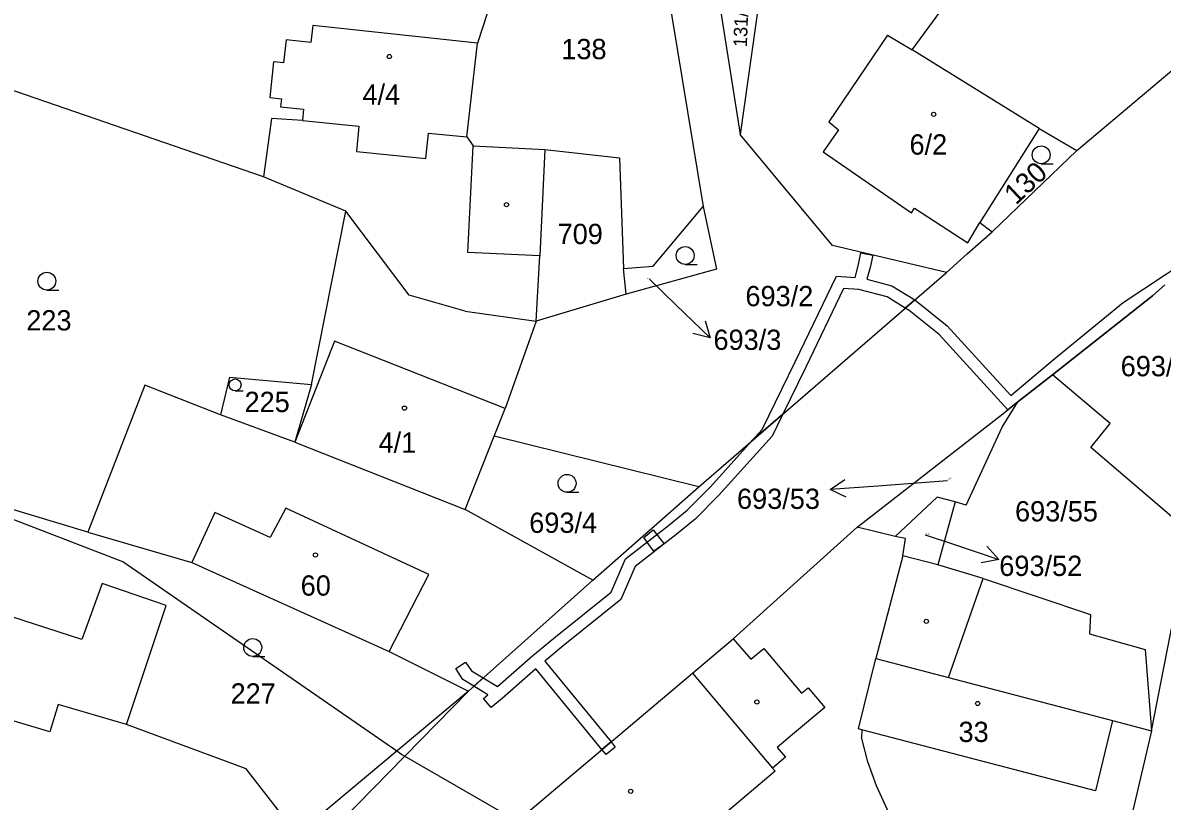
# Model space of a CAD drawing. Extents: x -747333 to -745433, y -1133152 to -1130600.
# Drawn here: x -746537.7 to -746442.1, y -1132077.2 to -1132011.9 of the extents above; entities that cross this region are included whole.
import ezdxf

# ---------------------------------------------------------------- set-up
doc = ezdxf.new("R2010")
doc.units = 0
for name, color, linetype in [('Vrstva 1', 7, 'Continuous'), ('Vrstva 16', 7, 'Continuous'), ('Vrstva 18', 7, 'Continuous'), ('Vrstva 19', 7, 'Continuous'), ('Vrstva 25', 7, 'Continuous'), ('Vrstva 3', 7, 'Continuous'), ('Vrstva 30', 7, 'Continuous'), ('Vrstva 37', 7, 'Continuous'), ('Vrstva 4', 7, 'Continuous'), ('Vrstva 52', 7, 'Continuous'), ('Vrstva 6', 7, 'Continuous')]:
    doc.layers.add(name, color=color, linetype=linetype)

msp = doc.modelspace()

# ---------------------------------------------------------------- linework, layer by layer
at = {"layer": 'Vrstva 1'}
msp.add_line((-746464.74, -1132078.87), (-746466.1, -1132075.88), dxfattribs=at)
for points in [[(-746485.89, -1131995.45), (-746480.65, -1132027.32)], [(-746494.93, -1131999.39), (-746499.57, -1132013.64)], [(-746479.42, -1132009.41), (-746477.54, -1132021.27)], [(-746475.88, -1132009.57), (-746477.54, -1132021.27)], [(-746463.13, -1132014.2), (-746460.4, -1132010.51)], [(-746513.39, -1132012.14), (-746513.55, -1132013.58)], [(-746499.57, -1132013.64), (-746513.39, -1132012.14)], [(-746515.63, -1132013.35), (-746515.84, -1132015.29)], [(-746513.55, -1132013.58), (-746515.63, -1132013.35)], [(-746465.2, -1132012.95), (-746470.12, -1132020.21)], [(-746465.2, -1132012.95), (-746463.13, -1132014.2)], [(-746500.46, -1132021.48), (-746499.57, -1132013.64)], [(-746449.32, -1132022.63), (-746438.69, -1132013.68)], [(-746517.52, -1132024.84), (-746547.41, -1132014.55)], [(-746516.68, -1132015.19), (-746517, -1132018.17)], [(-746515.84, -1132015.29), (-746516.68, -1132015.19)], [(-746517, -1132018.17), (-746516.01, -1132018.28)], [(-746516.01, -1132018.28), (-746516.08, -1132018.96)], [(-746516.08, -1132018.96), (-746514.15, -1132019.17)], [(-746514.15, -1132019.17), (-746514.25, -1132020.11)], [(-746516.85, -1132019.93), (-746517.52, -1132024.84)], [(-746514.25, -1132020.11), (-746516.85, -1132019.93)], [(-746469.3, -1132020.9), (-746470.59, -1132022.75)], [(-746470.12, -1132020.21), (-746469.3, -1132020.9)], [(-746452.47, -1132020.78), (-746457.44, -1132028.67)], [(-746452.47, -1132020.78), (-746449.32, -1132022.63)], [(-746500.46, -1132021.48), (-746499.94, -1132022.24)], [(-746469.81, -1132030.6), (-746477.54, -1132021.27)], [(-746499.94, -1132022.24), (-746493.92, -1132022.53)], [(-746493.92, -1132022.53), (-746494.35, -1132031.46)], [(-746493.92, -1132022.53), (-746487.66, -1132023.23)], [(-746470.59, -1132022.75), (-746463.17, -1132027.85)], [(-746456.4, -1132029.43), (-746449.32, -1132022.63)], [(-746487.66, -1132023.23), (-746487.32, -1132032.51)], [(-746510.62, -1132027.7), (-746517.52, -1132024.84)], [(-746513.48, -1132042.23), (-746510.62, -1132027.7)], [(-746505.29, -1132034.76), (-746510.62, -1132027.7)], [(-746484.84, -1132032.33), (-746480.65, -1132027.32)], [(-746480.65, -1132027.32), (-746479.53, -1132032.56)], [(-746463.17, -1132027.85), (-746462.91, -1132027.46)], [(-746462.91, -1132027.46), (-746458.46, -1132030.36)], [(-746458.46, -1132030.36), (-746457.44, -1132028.67)], [(-746457.44, -1132028.67), (-746456.4, -1132029.43)], [(-746458.5, -1132031.29), (-746456.4, -1132029.43)], [(-746460.24, -1132032.84), (-746469.81, -1132030.6)], [(-746494.65, -1132036.93), (-746494.35, -1132031.46)], [(-746460.24, -1132032.84), (-746458.5, -1132031.29)], [(-746487.32, -1132032.51), (-746484.84, -1132032.33)], [(-746487.1, -1132034.68), (-746487.32, -1132032.51)], [(-746479.53, -1132032.56), (-746487.1, -1132034.68)], [(-746481.01, -1132050.82), (-746460.24, -1132032.84)], [(-746442.97, -1132034.81), (-746441.94, -1132033.89)], [(-746500.61, -1132036.09), (-746505.29, -1132034.76)], [(-746487.1, -1132034.68), (-746494.65, -1132036.93)], [(-746451.35, -1132041.44), (-746442.97, -1132034.81)], [(-746500.61, -1132036.09), (-746494.65, -1132036.93)], [(-746494.65, -1132036.93), (-746497.26, -1132044.25)], [(-746520.36, -1132041.62), (-746521.13, -1132044.79)], [(-746520.36, -1132041.62), (-746513.48, -1132042.23)], [(-746454.25, -1132043.7), (-746451.35, -1132041.44)], [(-746527.47, -1132042.31), (-746532.26, -1132054.61)], [(-746521.13, -1132044.79), (-746527.47, -1132042.31)], [(-746513.48, -1132042.23), (-746514.9, -1132047.08)], [(-746455.77, -1132044.89), (-746454.25, -1132043.7)], [(-746514.9, -1132047.08), (-746521.13, -1132044.79)], [(-746498.18, -1132046.57), (-746497.26, -1132044.25)], [(-746467.74, -1132054.2), (-746455.77, -1132044.89)], [(-746532.26, -1132054.61), (-746561.87, -1132045.71)], [(-746500.6, -1132052.72), (-746498.18, -1132046.57)], [(-746481.01, -1132050.82), (-746498.18, -1132046.57)], [(-746514.9, -1132047.08), (-746500.6, -1132052.72)], [(-746489.9, -1132058.63), (-746481.01, -1132050.82)], [(-746489.9, -1132058.63), (-746500.6, -1132052.72)], [(-746478.14, -1132063.56), (-746467.74, -1132054.2)], [(-746464.53, -1132054.98), (-746467.74, -1132054.2)], [(-746532.26, -1132054.61), (-746523.53, -1132057.16)], [(-746463.68, -1132055.15), (-746464.53, -1132054.98)], [(-746463.9, -1132056.59), (-746463.68, -1132055.15)], [(-746523.53, -1132057.16), (-746506.99, -1132064.63)], [(-746463.9, -1132056.59), (-746466.16, -1132065.2)], [(-746460.97, -1132057.37), (-746463.9, -1132056.59)], [(-746457.15, -1132058.5), (-746460.97, -1132057.37)], [(-746532.75, -1132063.63), (-746550.3, -1132057.95)], [(-746531.05, -1132058.91), (-746532.75, -1132063.63)], [(-746525.69, -1132060.77), (-746531.05, -1132058.91)], [(-746500.33, -1132067.94), (-746489.9, -1132058.63)], [(-746457.15, -1132058.5), (-746448.17, -1132061.53)], [(-746529.02, -1132070.74), (-746525.69, -1132060.77)], [(-746448.17, -1132061.53), (-746448.25, -1132063.14)], [(-746448.25, -1132063.14), (-746443.57, -1132064.45)], [(-746481.55, -1132066.44), (-746478.14, -1132063.56)], [(-746506.99, -1132064.63), (-746500.33, -1132067.94)], [(-746443.57, -1132064.45), (-746443.05, -1132071.26)], [(-746467.62, -1132071.1), (-746466.16, -1132065.2)], [(-746498.03, -1132080.35), (-746481.55, -1132066.44)], [(-746525.66, -1132093.79), (-746500.33, -1132067.94)], [(-746500.33, -1132067.94), (-746514.69, -1132079.97)], [(-746518.97, -1132074.45), (-746529.02, -1132070.74)], [(-746446.32, -1132070.4), (-746447.75, -1132076.29)], [(-746446.32, -1132070.4), (-746443.05, -1132071.26)], [(-746467.33, -1132071.18), (-746467.62, -1132071.1)], [(-746467.33, -1132071.18), (-746467.37, -1132071.81)], [(-746447.75, -1132076.29), (-746467.33, -1132071.18)], [(-746443.05, -1132071.26), (-746448.34, -1132093.81)], [(-746466.83, -1132073.88), (-746467.37, -1132071.81)], [(-746514.69, -1132079.97), (-746518.97, -1132074.45)], [(-746466.1, -1132075.88), (-746466.83, -1132073.88)]]:
    msp.add_lwpolyline(points, dxfattribs=at)
at = {"layer": 'Vrstva 16'}
for p, q in [((-746480.476833, -1132036.896154), (-746480.062733, -1132038.338729)), ((-746468.647811, -1132051.695755), (-746469.999255, -1132051.042992)), ((-746456.851891, -1132055.781943), (-746455.859647, -1132056.907977))]:
    msp.add_line(p, q, dxfattribs=at)
for points in [[(-746485.16, -1132033.41), (-746482.94, -1132035.56)], [(-746482.94, -1132035.56), (-746480.062733, -1132038.338729), (-746481.518856, -1132037.97513)], [(-746466.01, -1132050.75), (-746469.999255, -1132051.042992), (-746468.757683, -1132050.199785)], [(-746460.15, -1132050.32), (-746466.01, -1132050.75)], [(-746462.03, -1132054.83), (-746459.65, -1132055.63)], [(-746459.65, -1132055.63), (-746455.859647, -1132056.907977), (-746457.331132, -1132057.203326)]]:
    msp.add_lwpolyline(points, dxfattribs=at)
at = {"layer": 'Vrstva 25'}
for p, q in [((-746452.3, -1132023.74), (-746451.3, -1132023.74)), ((-746482.15, -1132032.18), (-746481.15, -1132032.18)), ((-746535.69, -1132034.33), (-746534.69, -1132034.33)), ((-746519.9, -1132042.78), (-746519.23, -1132042.78)), ((-746492.06, -1132051.28), (-746491.06, -1132051.28)), ((-746518.42, -1132065.04), (-746517.42, -1132065.04))]:
    msp.add_line(p, q, dxfattribs=at)
for centre, radius in [((-746506.97, -1132014.75), 0.174503), ((-746461.32, -1132019.59), 0.174503), ((-746452.3, -1132022.99), 0.75), ((-746497.14, -1132027.16), 0.174503), ((-746482.15, -1132031.43), 0.75), ((-746535.69, -1132033.58), 0.75), ((-746519.9, -1132042.2775), 0.5025), ((-746505.7, -1132044.22), 0.174503), ((-746492.06, -1132050.53), 0.75), ((-746513.16, -1132056.54), 0.174503), ((-746461.93, -1132062.09), 0.174503), ((-746518.42, -1132064.29), 0.75), ((-746476.14, -1132068.86), 0.174503), ((-746457.62, -1132068.98), 0.174503), ((-746486.72, -1132076.35), 0.174503)]:
    msp.add_circle(centre, radius, dxfattribs=at)
at = {"layer": 'Vrstva 3'}
for points in [[(-746513.39, -1132012.14), (-746513.55, -1132013.58)], [(-746499.57, -1132013.64), (-746513.39, -1132012.14)], [(-746515.63, -1132013.35), (-746515.84, -1132015.29)], [(-746513.55, -1132013.58), (-746515.63, -1132013.35)], [(-746465.2, -1132012.95), (-746470.12, -1132020.21)], [(-746465.2, -1132012.95), (-746463.13, -1132014.2)], [(-746500.46, -1132021.48), (-746499.57, -1132013.64)], [(-746452.47, -1132020.78), (-746463.13, -1132014.2)], [(-746516.68, -1132015.19), (-746517, -1132018.17)], [(-746515.84, -1132015.29), (-746516.68, -1132015.19)], [(-746517, -1132018.17), (-746516.01, -1132018.28)], [(-746516.01, -1132018.28), (-746516.08, -1132018.96)], [(-746516.08, -1132018.96), (-746514.15, -1132019.17)], [(-746514.15, -1132019.17), (-746514.25, -1132020.11)], [(-746514.25, -1132020.11), (-746509.52, -1132020.58)], [(-746509.52, -1132020.58), (-746509.73, -1132022.72)], [(-746469.3, -1132020.9), (-746470.59, -1132022.75)], [(-746470.12, -1132020.21), (-746469.3, -1132020.9)], [(-746452.47, -1132020.78), (-746457.44, -1132028.67)], [(-746503.91, -1132023.3), (-746503.69, -1132021.16)], [(-746503.69, -1132021.16), (-746500.46, -1132021.48)], [(-746509.73, -1132022.72), (-746503.91, -1132023.3)], [(-746470.59, -1132022.75), (-746463.17, -1132027.85)], [(-746463.17, -1132027.85), (-746462.91, -1132027.46)], [(-746462.91, -1132027.46), (-746458.46, -1132030.36)], [(-746458.46, -1132030.36), (-746457.44, -1132028.67)], [(-746511.56, -1132038.61), (-746514.9, -1132047.08)], [(-746497.26, -1132044.25), (-746511.56, -1132038.61)], [(-746498.18, -1132046.57), (-746497.26, -1132044.25)], [(-746500.6, -1132052.72), (-746498.18, -1132046.57)], [(-746514.9, -1132047.08), (-746500.6, -1132052.72)], [(-746515.64, -1132052.6), (-746516.95, -1132055.07)], [(-746503.66, -1132058.16), (-746515.64, -1132052.6)], [(-746521.59, -1132052.98), (-746523.53, -1132057.16)], [(-746516.95, -1132055.07), (-746521.59, -1132052.98)], [(-746523.53, -1132057.16), (-746506.99, -1132064.63)], [(-746506.99, -1132064.63), (-746503.66, -1132058.16)], [(-746467.62, -1132071.1), (-746466.16, -1132065.2)], [(-746466.16, -1132065.2), (-746460.07, -1132066.8)], [(-746498.03, -1132080.35), (-746481.55, -1132066.44)], [(-746481.55, -1132066.44), (-746474.84, -1132074.39)], [(-746460.07, -1132066.8), (-746446.32, -1132070.4)], [(-746446.32, -1132070.4), (-746447.75, -1132076.29)], [(-746467.33, -1132071.18), (-746467.62, -1132071.1)], [(-746447.75, -1132076.29), (-746467.33, -1132071.18)], [(-746474.84, -1132074.39), (-746474.61, -1132074.66)], [(-746475.14, -1132075.1), (-746479.87, -1132079.1)], [(-746474.61, -1132074.66), (-746475.14, -1132075.1)]]:
    msp.add_lwpolyline(points, dxfattribs=at)
at = {"layer": 'Vrstva 30'}
for p, q in [((-746485.63, -1132055.06), (-746484.83, -1132054.41)), ((-746484.83, -1132054.41), (-746484.27, -1132055.15)), ((-746485.05, -1132055.84), (-746485.63, -1132055.06)), ((-746484.27, -1132055.15), (-746483.93, -1132055.6)), ((-746484.77, -1132056.22), (-746485.05, -1132055.84)), ((-746483.93, -1132055.6), (-746484.77, -1132056.22))]:
    msp.add_line(p, q, dxfattribs=at)
for points in [[(-746467.61, -1132032.18), (-746467.41, -1132031.21)], [(-746467.41, -1132031.21), (-746466.43, -1132031.41)], [(-746466.43, -1132031.41), (-746466.63, -1132032.42)], [(-746467.91, -1132033.26), (-746467.61, -1132032.18)], [(-746466.63, -1132032.42), (-746466.91, -1132033.42)], [(-746445.41, -1132035.38), (-746440.13, -1132031.87)], [(-746472.94, -1132040.35), (-746469.47, -1132033.16)], [(-746469.47, -1132033.16), (-746467.91, -1132033.26)], [(-746466.91, -1132033.42), (-746464.81, -1132033.97)], [(-746468.87, -1132034.2), (-746472.04, -1132040.79)], [(-746467.6, -1132034.28), (-746468.87, -1132034.2)], [(-746465.21, -1132034.89), (-746467.6, -1132034.28)], [(-746464.81, -1132033.97), (-746462.9, -1132035.14)], [(-746441.94, -1132033.89), (-746442.97, -1132034.81)], [(-746463.7, -1132035.83), (-746465.21, -1132034.89)], [(-746462.9, -1132035.14), (-746463.7, -1132035.83)], [(-746463.7, -1132035.83), (-746462.9, -1132035.14)], [(-746462.9, -1132035.14), (-746460.17, -1132037.33)], [(-746442.97, -1132034.81), (-746451.35, -1132041.44)], [(-746451.28, -1132040.16), (-746445.41, -1132035.38)], [(-746463.36, -1132036.04), (-746463.7, -1132035.83)], [(-746460.85, -1132038.05), (-746463.36, -1132036.04)], [(-746460.17, -1132037.33), (-746454.84, -1132043.15)], [(-746455.09, -1132044.36), (-746460.85, -1132038.05)], [(-746454.84, -1132043.15), (-746451.28, -1132040.16)], [(-746475.71, -1132046.02), (-746472.94, -1132040.35)], [(-746472.04, -1132040.79), (-746473.96, -1132044.72)], [(-746451.35, -1132041.44), (-746454.25, -1132043.7)], [(-746454.25, -1132043.7), (-746455.09, -1132044.36)], [(-746473.96, -1132044.72), (-746476.58, -1132046.99)], [(-746476.58, -1132046.99), (-746473.96, -1132044.72)], [(-746473.96, -1132044.72), (-746474.87, -1132046.58)], [(-746474.87, -1132046.58), (-746479.32, -1132051.51)], [(-746476.58, -1132046.99), (-746475.71, -1132046.02)], [(-746480.04, -1132050.82), (-746476.58, -1132046.99)], [(-746482, -1132052.78), (-746480.04, -1132050.82)], [(-746479.32, -1132051.51), (-746481.32, -1132053.52)], [(-746483.56, -1132054.05), (-746482, -1132052.78)], [(-746481.32, -1132053.52), (-746482.94, -1132054.83)], [(-746487.16, -1132056.85), (-746483.56, -1132054.05)], [(-746482.94, -1132054.83), (-746486.34, -1132057.49)], [(-746488.37, -1132059.64), (-746487.16, -1132056.85)], [(-746486.34, -1132057.49), (-746487.55, -1132060.26)], [(-746493.02, -1132063.38), (-746488.37, -1132059.64)], [(-746487.55, -1132060.26), (-746492.38, -1132064.16)], [(-746494.93, -1132064.96), (-746493.02, -1132063.38)], [(-746497.89, -1132067.57), (-746494.93, -1132064.96)], [(-746492.38, -1132064.16), (-746493.93, -1132065.43)], [(-746501.4, -1132066.06), (-746500.57, -1132065.51)], [(-746500.57, -1132065.51), (-746500.08, -1132066.24)], [(-746493.93, -1132065.43), (-746488.37, -1132072.2)], [(-746500.8, -1132066.98), (-746501.4, -1132066.06)], [(-746500.08, -1132066.24), (-746499.1, -1132066.84)], [(-746499.88, -1132067.54), (-746499.1, -1132066.84)], [(-746499.1, -1132066.84), (-746499.88, -1132067.54)], [(-746499.1, -1132066.84), (-746497.89, -1132067.57)], [(-746494.69, -1132066.08), (-746497.51, -1132068.57)], [(-746489.14, -1132072.84), (-746494.69, -1132066.08)], [(-746499.88, -1132067.54), (-746500.8, -1132066.98)], [(-746498.7, -1132068.26), (-746499.88, -1132067.54)], [(-746499.06, -1132068.57), (-746498.7, -1132068.26)], [(-746498.42, -1132069.33), (-746499.06, -1132068.57)], [(-746497.51, -1132068.57), (-746498.42, -1132069.33)], [(-746488.37, -1132072.2), (-746489.14, -1132072.84)], [(-746489.14, -1132072.84), (-746488.37, -1132072.2)], [(-746488.02, -1132072.63), (-746488.79, -1132073.27)], [(-746488.37, -1132072.2), (-746488.02, -1132072.63)], [(-746488.79, -1132073.27), (-746489.14, -1132072.84)]]:
    msp.add_lwpolyline(points, dxfattribs=at)
at = {"layer": 'Vrstva 37'}
for centre in [(-746506.97, -1132014.75), (-746461.32, -1132019.59), (-746505.7, -1132044.22), (-746513.16, -1132056.54), (-746457.62, -1132068.98), (-746486.72, -1132076.35)]:
    msp.add_circle(centre, 0.174503, dxfattribs=at)
at = {"layer": 'Vrstva 4'}
for points in [[(-746452.47, -1132020.78), (-746463.13, -1132014.2)], [(-746514.25, -1132020.11), (-746509.52, -1132020.58)], [(-746509.52, -1132020.58), (-746509.73, -1132022.72)], [(-746503.91, -1132023.3), (-746503.69, -1132021.16)], [(-746503.69, -1132021.16), (-746500.46, -1132021.48)], [(-746509.73, -1132022.72), (-746503.91, -1132023.3)], [(-746500.37, -1132031.17), (-746499.94, -1132022.24)], [(-746494.35, -1132031.46), (-746500.37, -1132031.17)], [(-746511.56, -1132038.61), (-746514.9, -1132047.08)], [(-746497.26, -1132044.25), (-746511.56, -1132038.61)], [(-746515.64, -1132052.6), (-746516.95, -1132055.07)], [(-746503.66, -1132058.16), (-746515.64, -1132052.6)], [(-746521.59, -1132052.98), (-746523.53, -1132057.16)], [(-746516.95, -1132055.07), (-746521.59, -1132052.98)], [(-746506.99, -1132064.63), (-746503.66, -1132058.16)], [(-746460.07, -1132066.8), (-746457.15, -1132058.5)], [(-746478.14, -1132063.56), (-746476.64, -1132065.26)], [(-746476.64, -1132065.26), (-746475.57, -1132064.36)], [(-746475.57, -1132064.36), (-746472.39, -1132068.12)], [(-746466.16, -1132065.2), (-746460.07, -1132066.8)], [(-746481.55, -1132066.44), (-746474.84, -1132074.39)], [(-746460.07, -1132066.8), (-746446.32, -1132070.4)], [(-746472.39, -1132068.12), (-746471.83, -1132067.66)], [(-746471.83, -1132067.66), (-746470.44, -1132069.31)], [(-746535.43, -1132071.36), (-746540.61, -1132069.81)], [(-746534.75, -1132069.06), (-746535.43, -1132071.36)], [(-746529.02, -1132070.74), (-746534.75, -1132069.06)], [(-746470.44, -1132069.31), (-746473.14, -1132071.58)], [(-746473.14, -1132071.58), (-746474.43, -1132072.67)], [(-746474.43, -1132072.67), (-746473.75, -1132073.47)], [(-746473.75, -1132073.47), (-746474.84, -1132074.39)], [(-746474.84, -1132074.39), (-746474.61, -1132074.66)], [(-746475.14, -1132075.1), (-746479.87, -1132079.1)], [(-746474.61, -1132074.66), (-746475.14, -1132075.1)]]:
    msp.add_lwpolyline(points, dxfattribs=at)
at = {"layer": 'Vrstva 52'}
msp.add_lwpolyline([(-746438.31, -1132090.25), (-746447.63, -1132090.8), (-746452.17, -1132091.07), (-746452.91, -1132091.11), (-746453.19, -1132091.13), (-746473.32, -1132088.39), (-746475.12, -1132088.15), (-746475.31, -1132088.12), (-746483.46, -1132084.59), (-746494.87, -1132079.63), (-746496.24, -1132078.84), (-746505.68, -1132073.4), (-746505.94, -1132073.25), (-746506.34, -1132072.97), (-746529.31, -1132057.12), (-746540.37, -1132052.87), (-746543.8, -1132051.14), (-746560.48, -1132042.71), (-746561.63, -1132042.13), (-746571.81, -1132033.63)], dxfattribs=at)
at = {"layer": 'Vrstva 6'}
for points in [[(-746446.52, -1132045.51), (-746451.35, -1132041.44)], [(-746455.58, -1132045.82), (-746454.25, -1132043.7)], [(-746458.58, -1132052.35), (-746455.58, -1132045.82)], [(-746448.13, -1132047.51), (-746446.52, -1132045.51)], [(-746440.99, -1132053.65), (-746448.13, -1132047.51)], [(-746461.03, -1132051.69), (-746464.53, -1132054.98)], [(-746459.5, -1132052.08), (-746461.03, -1132051.69)], [(-746459.5, -1132052.08), (-746460.97, -1132057.37)], [(-746458.58, -1132052.35), (-746459.5, -1132052.08)], [(-746443.05, -1132071.26), (-746440.38, -1132057.72)]]:
    msp.add_lwpolyline(points, dxfattribs=at)

# ---------------------------------------------------------------- texts
at = {"layer": 'Vrstva 16'}
for s, p in [('693/3', (-746479.78, -1132039.34)), ('693/53', (-746477.806335, -1132052.67)), ('693/52', (-746455.81, -1132058.29))]:
    msp.add_text(s, height=1.7, dxfattribs=at).set_placement(p)
at = {"layer": 'Vrstva 18'}
for s, height, rotation, p in [('131/11', 1.14, 87.89832, (-746476.98, -1132013.97)), ('130', 1.7, 43.08597, (-746454.42, -1132027.25)), ('693/53', 0.1, 36.08298, (-746460.15, -1132050.32))]:
    msp.add_text(s, height=height, rotation=rotation, dxfattribs=at).set_placement(p)
for s, height, p in [('138', 1.7, (-746492.54, -1132014.97)), ('709', 1.7, (-746492.852407, -1132030.47)), ('693/3', 0.1, (-746485.349999, -1132033.41)), ('693/2', 1.7, (-746477.1, -1132035.68)), ('223', 1.7, (-746537.41, -1132037.71)), ('693/56', 1.7, (-746445.63, -1132041.55)), ('225', 1.7, (-746519.11, -1132044.55)), ('693/55', 1.7, (-746454.49, -1132053.72)), ('693/4', 1.7, (-746495.23, -1132054.68)), ('693/52', 0.1, (-746462.03, -1132054.83)), ('227', 1.7, (-746520.28, -1132068.99))]:
    msp.add_text(s, height=height, dxfattribs=at).set_placement(p)
at = {"layer": 'Vrstva 19'}
for s, p in [('4/4', (-746509.22, -1132018.79)), ('6/2', (-746463.34, -1132022.97)), ('4/1', (-746507.87, -1132047.96)), ('60', (-746514.4, -1132059.94)), ('33', (-746459.23, -1132072.21))]:
    msp.add_text(s, height=1.7, dxfattribs=at).set_placement(p)

doc.saveas('drawing.dxf')
